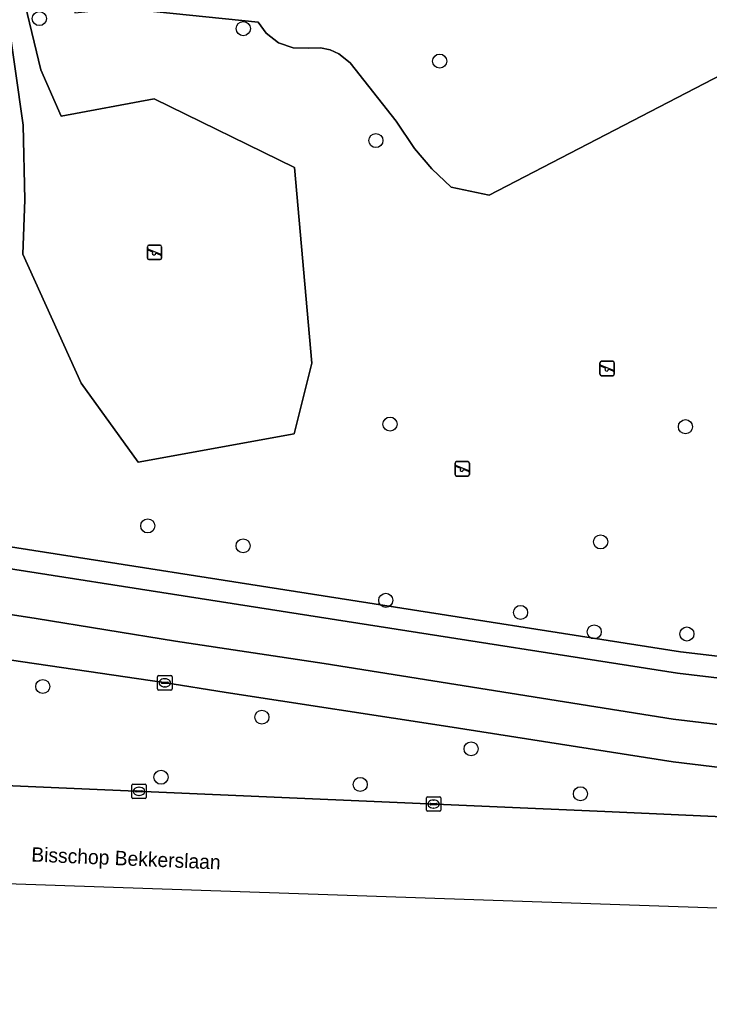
# Model space of a CAD drawing. Extents: x 160732 to 162107, y 387428 to 388479.
# Drawn here: x 160890.4 to 160938.3, y 387472.9 to 387541.9 of the extents above; entities that cross this region are included whole.
import ezdxf

# ---------------------------------------------------------------- set-up
doc = ezdxf.new("R2010")
doc.units = 0
for name, color, linetype in [('IMGEO_Berm_groen', 7, 'Continuous'), ('IMGEO_Boom', 7, 'Continuous'), ('IMGEO_Fietspad_open', 7, 'Continuous'), ('IMGEO_Groenvoorziening', 7, 'Continuous'), ('IMGEO_Hek', 7, 'Continuous'), ('IMGEO_Kolk', 7, 'Continuous'), ('IMGEO_Openbare_ruimte_label', 7, 'Continuous'), ('IMGEO_Rijbaan_lokaal_gesloten', 7, 'Continuous'), ('IMGEO_Speelvoorziening', 7, 'Continuous'), ('IMGEO_Terreindeel_zand', 7, 'Continuous'), ('IMGEO_Verkeerseiland_groen', 7, 'Continuous'), ('IMGEO_Voetpad_open', 7, 'Continuous')]:
    doc.layers.add(name, color=color, linetype=linetype)

msp = doc.modelspace()

# ---------------------------------------------------------------- linework, layer by layer
at = {"layer": 'IMGEO_Berm_groen'}
msp.add_lwpolyline([(160959.916, 387496.024), (160946.169, 387496.849), (160936.309, 387498.011), (160889.009, 387505.413), (160806.924, 387518.259), (160800.367, 387617.785), (160799.877, 387625.216), (160797.423, 387625.06), (160796.815, 387625.004), (160797.074, 387620.896), (160803.773, 387517.234), (160913.899, 387500), (160936.105, 387496.525), (160946.036, 387495.354), (160959.839, 387494.526), (160979.097, 387493.706), (160979.317, 387493.697), (160979.564, 387495.188), (160978.599, 387495.229)], close=True, dxfattribs=at)
at = {"layer": 'IMGEO_Boom'}
for centre in [(160891.771, 387542.021), (160905.938, 387541.325), (160919.578, 387539.065), (160915.146, 387533.543), (160916.129, 387513.834), (160936.652, 387513.656), (160899.298, 387506.764), (160905.921, 387505.375), (160930.759, 387505.65), (160915.832, 387501.588), (160925.195, 387500.745), (160930.314, 387499.392), (160936.749, 387499.247), (160892.004, 387495.598), (160907.23, 387493.465), (160921.759, 387491.265), (160900.222, 387489.291), (160914.06, 387488.79), (160929.354, 387488.142)]:
    msp.add_circle(centre, 0.489, dxfattribs=at)
at = {"layer": 'IMGEO_Fietspad_open'}
for points in [[(161134.151, 387484.191), (161079.41, 387486.41), (161032.946, 387488.45), (161000, 387489.783), (160964.882, 387491.216), (160955.896, 387491.483), (160945.905, 387492.112), (160935.793, 387493.329), (160911.562, 387497.191), (160901.233, 387498.754), (160891.554, 387500.319), (160862.38, 387504.81), (160820.517, 387511.401), (160801.558, 387514.26)], [(160798.352, 387511.312), (160803.597, 387510.687), (160818.903, 387508.372), (160856.279, 387502.542), (160869.321, 387500.586), (160886.183, 387497.972), (160900.412, 387495.865), (160904.738, 387495.178), (160920.142, 387492.807), (160935.786, 387490.359), (160945.779, 387489.15), (160955.792, 387488.482), (160967.502, 387488.005), (160970.746, 387487.874), (160988.475, 387487.152), (161000, 387486.685), (161032.863, 387485.379), (161078.213, 387483.477), (161134.039, 387481.162), (161134.151, 387484.191)]]:
    msp.add_lwpolyline(points, dxfattribs=at)
at = {"layer": 'IMGEO_Groenvoorziening'}
for points in [[(160898.078, 387545.131), (160894.06, 387543.946), (160894.237, 387542.434), (160897.436, 387542.742), (160906.978, 387541.785), (160907.535, 387541.005), (160908.393, 387540.348), (160909.411, 387539.988), (160910.491, 387539.96), (160911.309, 387539.981), (160911.964, 387539.844), (160912.575, 387539.573), (160913.354, 387538.945), (160916.56, 387534.884), (160917.826, 387532.995), (160919.026, 387531.589), (160920.367, 387530.317), (160923.011, 387529.746), (160944.179, 387540.722)], [(160890.787, 387542.981), (160891.863, 387538.451), (160893.283, 387535.251), (160899.751, 387536.449), (160909.498, 387531.666), (160910.7, 387518.069), (160909.482, 387513.159), (160898.635, 387511.189), (160894.685, 387516.677), (160890.626, 387525.655), (160890.766, 387529.424), (160890.644, 387534.616), (160889.508, 387542.603), (160871.223, 387537.209), (160871.468, 387536.378), (160889.423, 387541.764), (160889.126, 387528.71), (160889.124, 387528.613), (160889.09, 387521.715), (160889.009, 387505.413), (160936.309, 387498.011), (160946.169, 387496.849)], [(160944.179, 387540.722), (160923.011, 387529.746), (160920.367, 387530.317), (160919.026, 387531.589), (160917.826, 387532.995), (160916.56, 387534.884), (160913.354, 387538.945), (160912.575, 387539.573), (160911.964, 387539.844), (160911.309, 387539.981), (160910.491, 387539.96), (160909.411, 387539.988), (160908.393, 387540.348), (160907.535, 387541.005), (160906.978, 387541.785), (160897.436, 387542.742)]]:
    msp.add_lwpolyline(points, dxfattribs=at)
at = {"layer": 'IMGEO_Hek'}
msp.add_lwpolyline([(160978.599, 387495.229), (160959.916, 387496.024), (160946.169, 387496.849), (160936.309, 387498.011), (160889.009, 387505.413)], dxfattribs=at)
at = {"layer": 'IMGEO_Kolk'}
for p, q in [((160899.988, 387495.428), (160899.988, 387496.28)), ((160900.063, 387496.354), (160900.915, 387496.354)), ((160900.989, 387496.28), (160900.989, 387495.428)), ((160900.247, 387495.848), (160900.247, 387495.86)), ((160900.685, 387495.811), (160900.287, 387495.811)), ((160900.29, 387495.897), (160900.688, 387495.897)), ((160900.499, 387495.574), (160900.474, 387495.574)), ((160900.476, 387496.134), (160900.501, 387496.134)), ((160900.731, 387495.86), (160900.731, 387495.848)), ((160900.915, 387495.354), (160900.063, 387495.354)), ((160898.193, 387487.886), (160898.193, 387488.738)), ((160898.268, 387488.812), (160899.12, 387488.812)), ((160898.681, 387488.592), (160898.706, 387488.592)), ((160899.194, 387488.738), (160899.194, 387487.886)), ((160898.452, 387488.306), (160898.452, 387488.318)), ((160898.89, 387488.269), (160898.492, 387488.269)), ((160898.495, 387488.355), (160898.893, 387488.355)), ((160898.704, 387488.032), (160898.679, 387488.032)), ((160898.936, 387488.318), (160898.936, 387488.306)), ((160918.73, 387487.923), (160919.582, 387487.923)), ((160899.12, 387487.812), (160898.268, 387487.812)), ((160918.655, 387486.997), (160918.655, 387487.849)), ((160918.914, 387487.417), (160918.914, 387487.429)), ((160919.352, 387487.38), (160918.954, 387487.38)), ((160918.957, 387487.466), (160919.355, 387487.466)), ((160919.143, 387487.703), (160919.168, 387487.703)), ((160919.398, 387487.429), (160919.398, 387487.417)), ((160919.656, 387487.849), (160919.656, 387486.997)), ((160919.582, 387486.923), (160918.73, 387486.923)), ((160919.166, 387487.143), (160919.141, 387487.143))]:
    msp.add_line(p, q, dxfattribs=at)
for points in [[(160899.988, 387495.428), (160899.988, 387496.28)], [(160900.063, 387496.354), (160900.915, 387496.354)], [(160900.989, 387496.28), (160900.989, 387495.428)], [(160900.915, 387495.354), (160900.063, 387495.354)], [(160898.193, 387487.886), (160898.193, 387488.738)], [(160898.268, 387488.812), (160899.12, 387488.812)], [(160899.194, 387488.738), (160899.194, 387487.886)], [(160918.73, 387487.923), (160919.582, 387487.923)], [(160899.12, 387487.812), (160898.268, 387487.812)], [(160918.655, 387486.997), (160918.655, 387487.849)], [(160919.656, 387487.849), (160919.656, 387486.997)], [(160919.582, 387486.923), (160918.73, 387486.923)]]:
    msp.add_lwpolyline(points, dxfattribs=at)
for centre, radius, start, end in [((160900.065, 387496.278), 0.0765, 91.55205, 178.44795), ((160900.065, 387496.278), 0.0765, 91.55205, 178.44795), ((160900.913, 387496.278), 0.0765, 1.55205, 88.44795), ((160900.913, 387496.278), 0.0765, 1.55205, 88.44795), ((160900.287, 387495.857), 0.0403, 85.87752, 175.75265), ((160900.284, 387495.847), 0.0366, 178.93798, 274.71019), ((160900.688, 387495.854), 0.043, 264.86636, 352.45326), ((160900.692, 387495.859), 0.0386, 1.73085, 96.63898), ((160900.065, 387495.43), 0.0765, 181.55205, 268.44795), ((160900.065, 387495.43), 0.0765, 181.55205, 268.44795), ((160900.913, 387495.43), 0.0765, 271.55205, 358.44795), ((160900.913, 387495.43), 0.0765, 271.55205, 358.44795), ((160898.27, 387488.736), 0.0765, 91.55205, 178.44795), ((160898.27, 387488.736), 0.0765, 91.55205, 178.44795), ((160899.118, 387488.736), 0.0765, 1.55205, 88.44795), ((160899.118, 387488.736), 0.0765, 1.55205, 88.44795), ((160898.27, 387487.888), 0.0765, 181.55205, 268.44795), ((160898.27, 387487.888), 0.0765, 181.55205, 268.44795), ((160898.492, 387488.315), 0.0403, 85.87752, 175.75265), ((160898.489, 387488.305), 0.0366, 178.93798, 274.71019), ((160898.893, 387488.312), 0.043, 264.86636, 352.45326), ((160898.897, 387488.317), 0.0386, 1.73085, 96.63898), ((160899.118, 387487.888), 0.0765, 271.55205, 358.44795), ((160899.118, 387487.888), 0.0765, 271.55205, 358.44795), ((160918.732, 387487.847), 0.0765, 91.55205, 178.44795), ((160918.732, 387487.847), 0.0765, 91.55205, 178.44795), ((160919.58, 387487.847), 0.0765, 1.55205, 88.44795), ((160919.58, 387487.847), 0.0765, 1.55205, 88.44795), ((160918.954, 387487.426), 0.0403, 85.87752, 175.75265), ((160918.951, 387487.416), 0.0366, 178.93798, 274.71019), ((160919.355, 387487.423), 0.043, 264.86636, 352.45326), ((160919.359, 387487.428), 0.0386, 1.73085, 96.63898), ((160918.732, 387486.999), 0.0765, 181.55205, 268.44795), ((160918.732, 387486.999), 0.0765, 181.55205, 268.44795), ((160919.58, 387486.999), 0.0765, 271.55205, 358.44795), ((160919.58, 387486.999), 0.0765, 271.55205, 358.44795)]:
    msp.add_arc(centre, radius, start, end, dxfattribs=at)
for centre, major_axis, ratio, start_param, end_param in [((160900.475, 387495.854), (-0.387, 0.002), 0.722429, 4.712389, 7.853982), ((160900.5, 387495.854), (-0.39, 0.002), 0.717154, 1.570796, 4.712389), ((160898.68, 387488.312), (-0.387, 0.002), 0.722429, 4.712389, 7.853982), ((160898.705, 387488.312), (-0.39, 0.002), 0.717154, 1.570796, 4.712389), ((160919.142, 387487.423), (-0.387, 0.002), 0.722429, 4.712389, 7.853982), ((160919.167, 387487.423), (-0.39, 0.002), 0.717154, 1.570796, 4.712389)]:
    msp.add_ellipse(centre, major_axis=major_axis, ratio=ratio, start_param=start_param, end_param=end_param, dxfattribs=at)
at = {"layer": 'IMGEO_Rijbaan_lokaal_gesloten'}
msp.add_lwpolyline([(160785.826, 387494.63), (160785.999, 387485.459), (161070.727, 387475.689), (161075.845, 387475.513), (161133.733, 387472.894), (161133.943, 387478.558), (161032.79, 387482.739), (161000, 387484.094), (160970.623, 387485.111), (160967.389, 387485.255), (160931.04, 387486.905), (160885.08, 387488.902), (160838.998, 387490.678), (160828.034, 387490.964), (160819.656, 387491.664), (160814.456, 387492.174), (160811.057, 387492.644), (160803.557, 387493.68), (160785.826, 387494.63)], dxfattribs=at)
at = {"layer": 'IMGEO_Speelvoorziening'}
for p, q in [((160899.275, 387525.369), (160899.275, 387526.169)), ((160899.275, 387526.169), (160899.275, 387525.369)), ((160899.658, 387525.797), (160899.319, 387525.934)), ((160899.344, 387525.994), (160900.22, 387525.641)), ((160899.375, 387526.269), (160900.165, 387526.269)), ((160900.165, 387526.269), (160899.375, 387526.269)), ((160900.265, 387526.169), (160900.265, 387525.369)), ((160900.265, 387525.369), (160900.265, 387526.169)), ((160900.165, 387525.269), (160899.375, 387525.269)), ((160899.375, 387525.269), (160900.165, 387525.269)), ((160900.196, 387525.581), (160899.856, 387525.718)), ((160930.714, 387517.303), (160930.714, 387518.103)), ((160930.714, 387518.103), (160930.714, 387517.303)), ((160931.097, 387517.731), (160930.758, 387517.868)), ((160930.783, 387517.928), (160931.659, 387517.575)), ((160930.814, 387518.203), (160931.604, 387518.203)), ((160931.604, 387518.203), (160930.814, 387518.203)), ((160931.635, 387517.515), (160931.295, 387517.652)), ((160931.704, 387518.103), (160931.704, 387517.303)), ((160931.704, 387517.303), (160931.704, 387518.103)), ((160931.604, 387517.203), (160930.814, 387517.203)), ((160930.814, 387517.203), (160931.604, 387517.203)), ((160920.654, 387510.329), (160920.654, 387511.129)), ((160920.654, 387511.129), (160920.654, 387510.329)), ((160921.037, 387510.757), (160920.698, 387510.894)), ((160920.723, 387510.954), (160921.599, 387510.601)), ((160920.754, 387511.229), (160921.544, 387511.229)), ((160921.544, 387511.229), (160920.754, 387511.229)), ((160921.575, 387510.541), (160921.235, 387510.678)), ((160921.644, 387511.129), (160921.644, 387510.329)), ((160921.644, 387510.329), (160921.644, 387511.129)), ((160921.544, 387510.229), (160920.754, 387510.229)), ((160920.754, 387510.229), (160921.544, 387510.229))]:
    msp.add_line(p, q, dxfattribs=at)
for centre, radius, start, end in [((160899.375, 387526.169), 0.1, 90, 180), ((160899.375, 387526.169), 0.1, 90, 180), ((160899.332, 387525.964), 0.0327, 68.07798, 248.07798), ((160900.165, 387526.169), 0.1, 0, 90), ((160900.165, 387526.169), 0.1, 360, 90), ((160899.375, 387525.369), 0.1, 180, 270), ((160899.375, 387525.369), 0.1, 180, 270), ((160899.737, 387525.707), 0.12, 130.99278, 5.16318), ((160900.165, 387525.369), 0.1, 270, 0), ((160900.165, 387525.369), 0.1, 270, 0), ((160900.208, 387525.611), 0.0327, 248.07798, 68.07798), ((160930.814, 387518.103), 0.1, 90, 180), ((160930.814, 387518.103), 0.1, 90, 180), ((160930.771, 387517.898), 0.0327, 68.07798, 248.07798), ((160931.176, 387517.641), 0.12, 130.99278, 5.16318), ((160931.604, 387518.103), 0.1, 0, 90), ((160931.604, 387518.103), 0.1, 360, 90), ((160931.647, 387517.545), 0.0327, 248.07798, 68.07798), ((160930.814, 387517.303), 0.1, 180, 270), ((160930.814, 387517.303), 0.1, 180, 270), ((160931.604, 387517.303), 0.1, 270, 0), ((160931.604, 387517.303), 0.1, 270, 0), ((160920.754, 387511.129), 0.1, 90, 180), ((160920.754, 387511.129), 0.1, 90, 180), ((160920.711, 387510.924), 0.0327, 68.07798, 248.07798), ((160921.116, 387510.667), 0.12, 130.99278, 5.16318), ((160921.544, 387511.129), 0.1, 0, 90), ((160921.544, 387511.129), 0.1, 360, 90), ((160920.754, 387510.329), 0.1, 180, 270), ((160920.754, 387510.329), 0.1, 180, 270), ((160921.544, 387510.329), 0.1, 270, 0), ((160921.544, 387510.329), 0.1, 270, 0), ((160921.587, 387510.571), 0.0327, 248.07798, 68.07798)]:
    msp.add_arc(centre, radius, start, end, dxfattribs=at)
at = {"layer": 'IMGEO_Terreindeel_zand'}
msp.add_lwpolyline([(160890.787, 387542.981), (160889.508, 387542.603), (160890.644, 387534.616), (160890.766, 387529.424), (160890.626, 387525.655), (160894.685, 387516.677), (160898.635, 387511.189), (160909.482, 387513.159), (160910.7, 387518.069), (160909.498, 387531.666), (160899.751, 387536.449), (160893.283, 387535.251), (160891.863, 387538.451)], close=True, dxfattribs=at)
at = {"layer": 'IMGEO_Verkeerseiland_groen'}
for points in [[(160904.738, 387495.178), (160900.412, 387495.865), (160886.183, 387497.972), (160869.321, 387500.586), (160856.279, 387502.542), (160818.903, 387508.372), (160803.597, 387510.687)], [(160801.81, 387509.204), (160802.218, 387505.574), (160803.397, 387505.707), (160803.837, 387501.792), (160802.658, 387501.659), (160802.845, 387500), (160803.557, 387493.68), (160811.057, 387492.644), (160814.456, 387492.174), (160819.656, 387491.664), (160828.034, 387490.964), (160838.998, 387490.678), (160885.08, 387488.902), (160931.04, 387486.905), (160967.389, 387485.255), (160967.502, 387488.005), (160955.792, 387488.482), (160945.779, 387489.15), (160935.786, 387490.359), (160920.142, 387492.807), (160904.738, 387495.178)]]:
    msp.add_lwpolyline(points, dxfattribs=at)
at = {"layer": 'IMGEO_Voetpad_open'}
for points in [[(161134.267, 387487.321), (161107.019, 387488.431), (161106.65, 387488.446), (161101.855, 387488.631), (161086.862, 387489.194), (161068.496, 387490.143), (161052.92, 387490.805), (161052.49, 387490.824), (161049.856, 387490.938), (161049.493, 387490.954), (161033.032, 387491.6), (161004.213, 387492.732), (161000, 387492.895), (160981.676, 387493.606), (160979.317, 387493.697), (160979.097, 387493.706), (160959.839, 387494.526), (160946.036, 387495.354), (160936.105, 387496.525), (160913.899, 387500), (160803.773, 387517.234), (160800.633, 387517.855)], [(160801.558, 387514.26), (160820.517, 387511.401), (160862.38, 387504.81), (160891.554, 387500.319), (160901.233, 387498.754), (160911.562, 387497.191), (160935.793, 387493.329), (160945.905, 387492.112), (160955.896, 387491.483), (160964.882, 387491.216), (161000, 387489.783), (161032.946, 387488.45), (161079.41, 387486.41), (161134.151, 387484.191), (161134.267, 387487.321)]]:
    msp.add_lwpolyline(points, dxfattribs=at)

# ---------------------------------------------------------------- texts
at = {"layer": 'IMGEO_Openbare_ruimte_label'}
msp.add_text('Bisschop Bekkerslaan', height=1, rotation=357.59259, dxfattribs=at).set_placement((160891.196, 387483.432))

doc.saveas('drawing.dxf')
